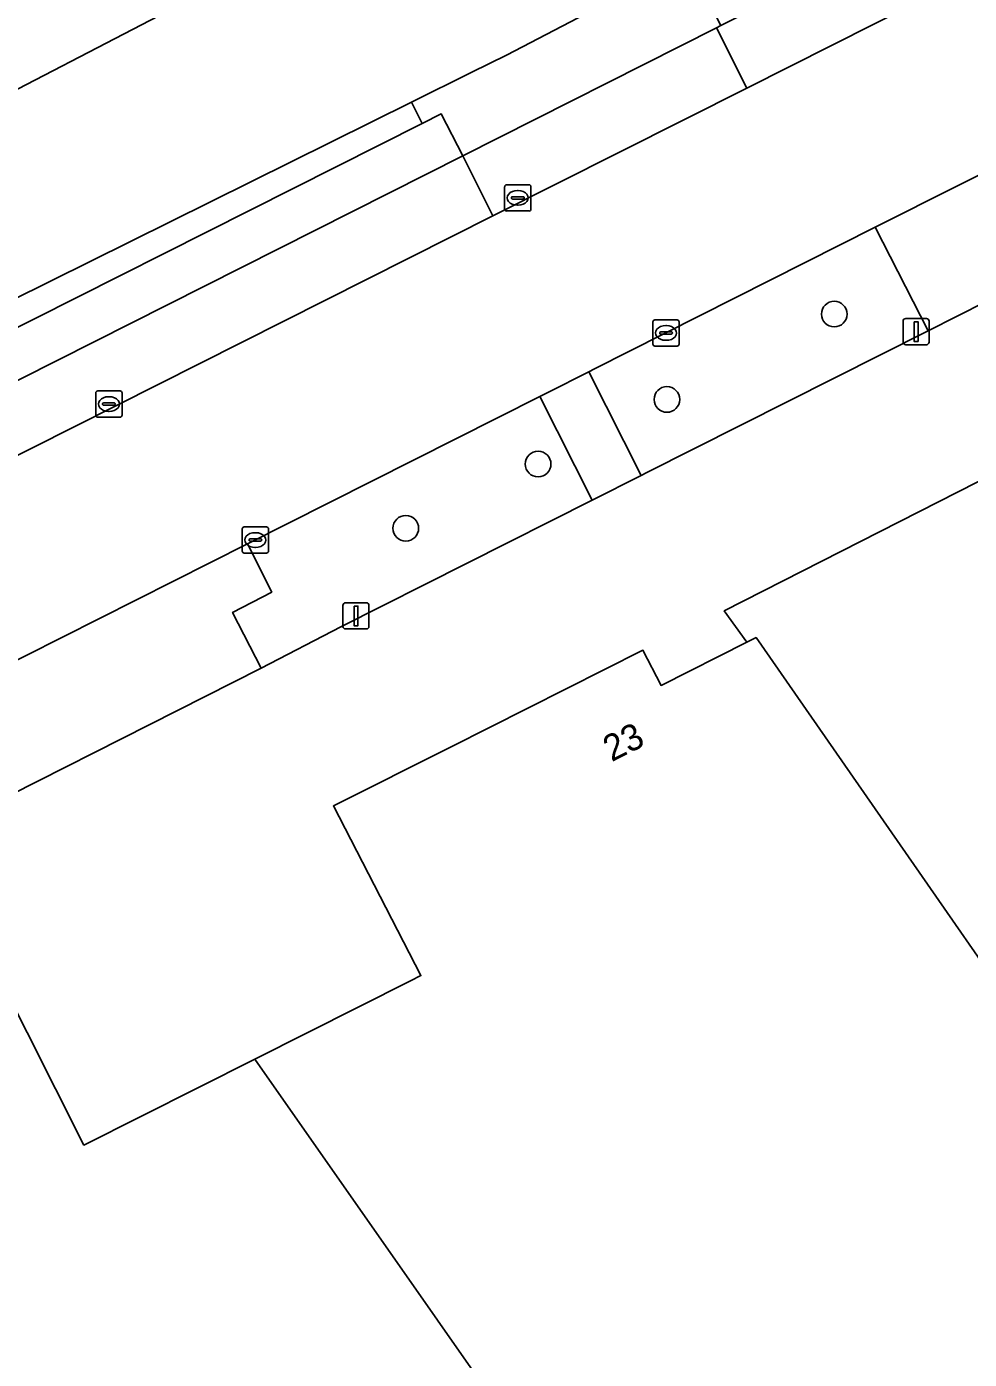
# Model space of a CAD drawing. Extents: x 156702 to 158052, y 387630 to 388992.
# Drawn here: x 157104.6 to 157140.6, y 388253.5 to 388304.3 of the extents above; entities that cross this region are included whole.
import ezdxf

# ---------------------------------------------------------------- set-up
doc = ezdxf.new("R2010")
doc.units = 0
for name, color, linetype in [('IMGEO_Berm_groen', 7, 'Continuous'), ('IMGEO_Boom', 7, 'Continuous'), ('IMGEO_Erf', 7, 'Continuous'), ('IMGEO_Groenvoorziening', 7, 'Continuous'), ('IMGEO_Hek', 7, 'Continuous'), ('IMGEO_Kolk', 7, 'Continuous'), ('IMGEO_Pand', 7, 'Continuous'), ('IMGEO_Pand_nummerreeks', 7, 'Continuous'), ('IMGEO_Parkeervlak_open', 7, 'Continuous'), ('IMGEO_Rijbaan_lokaal_gesloten', 7, 'Continuous'), ('IMGEO_Rijbaan_lokaal_open', 7, 'Continuous'), ('IMGEO_Verkeersbordpaal', 7, 'Continuous'), ('IMGEO_Voetpad_open', 7, 'Continuous')]:
    doc.layers.add(name, color=color, linetype=linetype)

msp = doc.modelspace()

# ---------------------------------------------------------------- linework, layer by layer
at = {"layer": 'IMGEO_Berm_groen'}
for points in [[(157138.985, 388292.726), (157136.976, 388296.673), (157126.271, 388291.273), (157126.055, 388291.164), (157128.049, 388287.211), (157128.27, 388287.322)], [(157126.181, 388286.269), (157124.187, 388290.222), (157114.576, 388285.374), (157113.037, 388284.606), (157113.966, 388282.763), (157112.472, 388281.984), (157113.566, 388279.867), (157116.605, 388281.44)]]:
    msp.add_lwpolyline(points, close=True, dxfattribs=at)
at = {"layer": 'IMGEO_Boom'}
for centre in [(157135.411, 388293.362), (157129.031, 388290.107), (157124.121, 388287.644), (157119.075, 388285.195)]:
    msp.add_circle(centre, 0.489, dxfattribs=at)
at = {"layer": 'IMGEO_Erf'}
for points in [[(157055.318, 388268.856), (157065.932, 388274.591), (157095.174, 388289.455), (157094.853, 388290.096), (157097.304, 388291.355), (157097.614, 388290.696), (157097.881, 388290.831), (157119.289, 388301.443), (157121.594, 388302.586), (157122.912, 388303.239), (157126.545, 388305.126), (157128.281, 388306.017), (157129.856, 388306.814), (157137.907, 388310.886), (157152.903, 388318.564), (157174.095, 388329.453), (157180.461, 388332.701), (157200.119, 388342.587), (157202.298, 388343.699), (157206.748, 388345.97), (157208.141, 388346.681), (157233.238, 388359.337)], [(157122.172, 388339.279), (157131.58, 388321.178), (157130.534, 388320.636), (157127.174, 388318.896), (157111.341, 388310.694), (157112.254, 388308.898), (157113.385, 388306.675), (157098.864, 388299.145), (157097.709, 388298.546), (157097.295, 388299.345), (157088.463, 388294.756), (157088.87, 388293.953), (157087.721, 388293.356), (157073.205, 388285.813), (157071.146, 388289.768), (157053.094, 388280.388)], [(157148.941, 388297.754), (157138.985, 388292.726), (157128.27, 388287.322), (157128.049, 388287.211), (157126.181, 388286.269), (157116.605, 388281.44), (157113.566, 388279.867), (157099.732, 388272.877), (157085.63, 388265.739), (157083.745, 388264.78), (157064.77, 388255.035), (157056.22, 388250.104), (157054.047, 388248.702), (157044.401, 388242.479)], [(157072.863, 388252.591), (157084.801, 388258.647), (157084.478, 388259.333), (157085.367, 388259.787), (157085.926, 388259.25), (157088.898, 388260.696), (157088.742, 388261.5), (157089.628, 388261.947), (157089.986, 388261.264), (157103.546, 388268.114), (157106.805, 388261.679), (157113.32, 388264.949), (157119.249, 388267.935), (157119.653, 388268.139), (157116.316, 388274.608), (157120.809, 388276.868), (157128.117, 388280.546), (157128.809, 388279.204), (157132.082, 388280.851), (157131.214, 388282.046), (157149.786, 388291.491)]]:
    msp.add_lwpolyline(points, dxfattribs=at)
at = {"layer": 'IMGEO_Groenvoorziening'}
msp.add_lwpolyline([(157119.694, 388300.635), (157119.289, 388301.443), (157097.881, 388290.831), (157098.352, 388289.876)], close=True, dxfattribs=at)
at = {"layer": 'IMGEO_Hek'}
msp.add_lwpolyline([(157121.594, 388302.586), (157119.289, 388301.443), (157097.881, 388290.831)], dxfattribs=at)
at = {"layer": 'IMGEO_Kolk'}
for p, q in [((157122.845, 388297.367), (157122.845, 388298.219)), ((157122.92, 388298.293), (157123.772, 388298.293)), ((157123.333, 388298.073), (157123.358, 388298.073)), ((157123.846, 388298.219), (157123.846, 388297.367)), ((157123.104, 388297.787), (157123.104, 388297.799)), ((157123.542, 388297.75), (157123.144, 388297.75)), ((157123.147, 388297.836), (157123.545, 388297.836)), ((157123.356, 388297.513), (157123.331, 388297.513)), ((157123.588, 388297.799), (157123.588, 388297.787)), ((157123.772, 388297.293), (157122.92, 388297.293)), ((157128.496, 388292.216), (157128.496, 388293.068)), ((157128.571, 388293.142), (157129.423, 388293.142)), ((157128.984, 388292.922), (157129.009, 388292.922)), ((157129.497, 388293.068), (157129.497, 388292.216)), ((157128.755, 388292.636), (157128.755, 388292.648)), ((157129.193, 388292.599), (157128.795, 388292.599)), ((157128.798, 388292.685), (157129.196, 388292.685)), ((157129.007, 388292.362), (157128.982, 388292.362)), ((157129.239, 388292.648), (157129.239, 388292.636)), ((157129.423, 388292.142), (157128.571, 388292.142)), ((157107.256, 388289.506), (157107.256, 388290.358)), ((157107.331, 388290.432), (157108.183, 388290.432)), ((157108.257, 388290.358), (157108.257, 388289.506)), ((157107.515, 388289.926), (157107.515, 388289.938)), ((157107.953, 388289.889), (157107.555, 388289.889)), ((157107.558, 388289.975), (157107.956, 388289.975)), ((157107.744, 388290.212), (157107.769, 388290.212)), ((157107.999, 388289.938), (157107.999, 388289.926)), ((157108.183, 388289.432), (157107.331, 388289.432)), ((157107.767, 388289.652), (157107.742, 388289.652)), ((157112.915, 388285.247), (157113.767, 388285.247)), ((157112.84, 388284.321), (157112.84, 388285.173)), ((157113.099, 388284.741), (157113.099, 388284.753)), ((157113.537, 388284.704), (157113.139, 388284.704)), ((157113.142, 388284.79), (157113.54, 388284.79)), ((157113.328, 388285.027), (157113.353, 388285.027)), ((157113.583, 388284.753), (157113.583, 388284.741)), ((157113.841, 388285.173), (157113.841, 388284.321)), ((157113.767, 388284.247), (157112.915, 388284.247)), ((157113.351, 388284.467), (157113.326, 388284.467))]:
    msp.add_line(p, q, dxfattribs=at)
for points in [[(157122.845, 388297.367), (157122.845, 388298.219)], [(157122.92, 388298.293), (157123.772, 388298.293)], [(157123.846, 388298.219), (157123.846, 388297.367)], [(157123.772, 388297.293), (157122.92, 388297.293)], [(157128.496, 388292.216), (157128.496, 388293.068)], [(157128.571, 388293.142), (157129.423, 388293.142)], [(157129.497, 388293.068), (157129.497, 388292.216)], [(157129.423, 388292.142), (157128.571, 388292.142)], [(157107.256, 388289.506), (157107.256, 388290.358)], [(157107.331, 388290.432), (157108.183, 388290.432)], [(157108.257, 388290.358), (157108.257, 388289.506)], [(157108.183, 388289.432), (157107.331, 388289.432)], [(157112.915, 388285.247), (157113.767, 388285.247)], [(157112.84, 388284.321), (157112.84, 388285.173)], [(157113.841, 388285.173), (157113.841, 388284.321)], [(157113.767, 388284.247), (157112.915, 388284.247)]]:
    msp.add_lwpolyline(points, dxfattribs=at)
for centre, radius, start, end in [((157122.922, 388298.217), 0.0765, 91.552, 178.448), ((157122.922, 388298.217), 0.0765, 91.552, 178.448), ((157123.77, 388298.217), 0.0765, 1.552, 88.448), ((157123.77, 388298.217), 0.0765, 1.552, 88.448), ((157123.144, 388297.796), 0.0403, 85.8775, 175.7526), ((157123.141, 388297.786), 0.0366, 178.938, 274.7102), ((157123.545, 388297.793), 0.043, 264.8664, 352.4533), ((157123.549, 388297.798), 0.0386, 1.7309, 96.639), ((157122.922, 388297.369), 0.0765, 181.552, 268.448), ((157122.922, 388297.369), 0.0765, 181.552, 268.448), ((157123.77, 388297.369), 0.0765, 271.552, 358.448), ((157123.77, 388297.369), 0.0765, 271.552, 358.448), ((157128.573, 388293.066), 0.0765, 91.552, 178.448), ((157128.573, 388293.066), 0.0765, 91.552, 178.448), ((157129.421, 388293.066), 0.0765, 1.552, 88.448), ((157129.421, 388293.066), 0.0765, 1.552, 88.448), ((157128.795, 388292.645), 0.0403, 85.8775, 175.7526), ((157128.792, 388292.635), 0.0366, 178.938, 274.7102), ((157129.196, 388292.642), 0.043, 264.8664, 352.4533), ((157129.2, 388292.647), 0.0386, 1.7309, 96.639), ((157128.573, 388292.218), 0.0765, 181.552, 268.448), ((157128.573, 388292.218), 0.0765, 181.552, 268.448), ((157129.421, 388292.218), 0.0765, 271.552, 358.448), ((157129.421, 388292.218), 0.0765, 271.552, 358.448), ((157107.333, 388290.356), 0.0765, 91.552, 178.448), ((157107.333, 388290.356), 0.0765, 91.552, 178.448), ((157108.181, 388290.356), 0.0765, 1.552, 88.448), ((157108.181, 388290.356), 0.0765, 1.552, 88.448), ((157107.555, 388289.935), 0.0403, 85.8775, 175.7526), ((157107.552, 388289.925), 0.0366, 178.938, 274.7102), ((157107.956, 388289.932), 0.043, 264.8664, 352.4533), ((157107.96, 388289.937), 0.0386, 1.7309, 96.639), ((157107.333, 388289.508), 0.0765, 181.552, 268.448), ((157107.333, 388289.508), 0.0765, 181.552, 268.448), ((157108.181, 388289.508), 0.0765, 271.552, 358.448), ((157108.181, 388289.508), 0.0765, 271.552, 358.448), ((157112.917, 388285.171), 0.0765, 91.552, 178.448), ((157112.917, 388285.171), 0.0765, 91.552, 178.448), ((157113.765, 388285.171), 0.0765, 1.552, 88.448), ((157113.765, 388285.171), 0.0765, 1.552, 88.448), ((157113.139, 388284.75), 0.0403, 85.8775, 175.7526), ((157113.136, 388284.74), 0.0366, 178.938, 274.7102), ((157113.54, 388284.747), 0.043, 264.8664, 352.4533), ((157113.544, 388284.752), 0.0386, 1.7309, 96.639), ((157112.917, 388284.323), 0.0765, 181.552, 268.448), ((157112.917, 388284.323), 0.0765, 181.552, 268.448), ((157113.765, 388284.323), 0.0765, 271.552, 358.448), ((157113.765, 388284.323), 0.0765, 271.552, 358.448)]:
    msp.add_arc(centre, radius, start, end, dxfattribs=at)
for centre, major_axis, ratio, start_param, end_param in [((157123.332, 388297.793), (-0.387, 0.002), 0.722429, 4.712389, 7.853982), ((157123.357, 388297.793), (-0.39, 0.002), 0.717154, 1.570796, 4.712389), ((157128.983, 388292.642), (-0.387, 0.002), 0.722429, 4.712389, 7.853982), ((157129.008, 388292.642), (-0.39, 0.002), 0.717154, 1.570796, 4.712389), ((157107.743, 388289.932), (-0.387, 0.002), 0.722429, 4.712389, 7.853982), ((157107.768, 388289.932), (-0.39, 0.002), 0.717154, 1.570796, 4.712389), ((157113.327, 388284.747), (-0.387, 0.002), 0.722429, 4.712389, 7.853982), ((157113.352, 388284.747), (-0.39, 0.002), 0.717154, 1.570796, 4.712389)]:
    msp.add_ellipse(centre, major_axis=major_axis, ratio=ratio, start_param=start_param, end_param=end_param, dxfattribs=at)
at = {"layer": 'IMGEO_Pand'}
msp.add_lwpolyline([(157053.094, 388280.388), (157071.146, 388289.768), (157073.205, 388285.813), (157087.721, 388293.356), (157088.87, 388293.953), (157088.463, 388294.756), (157097.295, 388299.345), (157097.709, 388298.546), (157098.864, 388299.145), (157113.385, 388306.675), (157112.254, 388308.898), (157111.341, 388310.694), (157127.174, 388318.896), (157130.534, 388320.636), (157131.58, 388321.178), (157122.172, 388339.279)], dxfattribs=at)
for points in [[(157150.298, 388290.598), (157150.383, 388290.659), (157149.786, 388291.491), (157131.214, 388282.046), (157132.082, 388280.851), (157132.433, 388281.028), (157148.354, 388258.104), (157151.414, 388253.673), (157168.087, 388265.189)], [(157132.433, 388281.028), (157132.082, 388280.851), (157128.809, 388279.204), (157128.117, 388280.546), (157120.809, 388276.868), (157116.316, 388274.608), (157119.653, 388268.139), (157119.249, 388267.935), (157113.32, 388264.949), (157134.3, 388234.974), (157156.538, 388246.255), (157151.414, 388253.673), (157148.354, 388258.104)], [(157113.32, 388264.949), (157106.805, 388261.679), (157103.546, 388268.114), (157089.986, 388261.264), (157089.628, 388261.947), (157088.742, 388261.5), (157088.898, 388260.696), (157085.926, 388259.25), (157085.367, 388259.787), (157084.478, 388259.333), (157084.801, 388258.647), (157072.863, 388252.591), (157074.168, 388250), (157076.091, 388246.183), (157074.559, 388245.319), (157077.424, 388241.221), (157095.536, 388215.309), (157134.3, 388234.974)]]:
    msp.add_lwpolyline(points, close=True, dxfattribs=at)
at = {"layer": 'IMGEO_Parkeervlak_open'}
msp.add_lwpolyline([(157138.553, 388305.245), (157137.409, 388307.516), (157131.09, 388304.366), (157130.915, 388304.277), (157132.072, 388301.981)], close=True, dxfattribs=at)
msp.add_lwpolyline([(157066.549, 388268.973), (157122.397, 388297.107), (157121.246, 388299.392), (157065.041, 388271.043), (157057.934, 388267.327), (157059.11, 388264.858)], dxfattribs=at)
at = {"layer": 'IMGEO_Rijbaan_lokaal_gesloten'}
for points in [[(157279.127, 388368.703), (157285.498, 388371.81), (157294.645, 388375.709), (157303.766, 388378.867), (157314.242, 388381.65), (157428.83, 388408.527), (157427.649, 388413.564), (157313.182, 388386.746), (157307.564, 388385.322), (157304.11, 388384.347), (157298.594, 388382.628), (157295.094, 388381.431), (157289.829, 388379.374), (157285.802, 388377.632), (157280.387, 388375.114), (157169.957, 388319.498), (157169.378, 388320.773), (157166.981, 388319.566), (157158.272, 388315.179), (157138.553, 388305.245), (157132.072, 388301.981), (157122.397, 388297.107), (157066.549, 388268.973)], [(157064.311, 388259.963), (157069.269, 388262.524), (157081.717, 388268.807), (157083.645, 388269.772), (157096.097, 388276.064), (157113.037, 388284.606), (157114.576, 388285.374), (157124.187, 388290.222), (157124.485, 388290.372), (157126.055, 388291.164), (157126.271, 388291.273), (157136.976, 388296.673), (157146.433, 388301.427), (157146.447, 388301.446), (157171.244, 388314.319), (157180.605, 388319.095), (157279.127, 388368.703)]]:
    msp.add_lwpolyline(points, dxfattribs=at)
at = {"layer": 'IMGEO_Rijbaan_lokaal_open'}
msp.add_lwpolyline([(157096.097, 388276.064), (157096.995, 388274.201), (157098.705, 388275.045), (157099.732, 388272.877), (157113.566, 388279.867), (157112.472, 388281.984), (157113.966, 388282.763), (157113.037, 388284.606)], close=True, dxfattribs=at)
at = {"layer": 'IMGEO_Verkeersbordpaal'}
for p, q in [((157138.035, 388292.293), (157138.035, 388293.093)), ((157138.035, 388293.093), (157138.035, 388292.293)), ((157138.135, 388293.193), (157138.925, 388293.193)), ((157138.925, 388293.193), (157138.135, 388293.193)), ((157139.025, 388293.093), (157139.025, 388292.293)), ((157139.025, 388292.293), (157139.025, 388293.093)), ((157138.925, 388292.193), (157138.135, 388292.193)), ((157138.135, 388292.193), (157138.925, 388292.193)), ((157116.681, 388281.456), (157116.681, 388282.256)), ((157116.681, 388282.256), (157116.681, 388281.456)), ((157116.781, 388282.356), (157117.571, 388282.356)), ((157117.571, 388282.356), (157116.781, 388282.356)), ((157117.671, 388282.256), (157117.671, 388281.456)), ((157117.671, 388281.456), (157117.671, 388282.256)), ((157117.571, 388281.356), (157116.781, 388281.356)), ((157116.781, 388281.356), (157117.571, 388281.356))]:
    msp.add_line(p, q, dxfattribs=at)
for points in [[(157138.455, 388293.068), (157138.605, 388293.068), (157138.605, 388292.318), (157138.455, 388292.318), (157138.455, 388293.068)], [(157117.101, 388282.231), (157117.251, 388282.231), (157117.251, 388281.481), (157117.101, 388281.481), (157117.101, 388282.231)]]:
    msp.add_lwpolyline(points, dxfattribs=at)
for centre, start, end in [((157138.135, 388293.093), 90, 180), ((157138.135, 388293.093), 90, 180), ((157138.925, 388293.093), 0, 90), ((157138.925, 388293.093), 360, 90), ((157138.135, 388292.293), 180, 270), ((157138.135, 388292.293), 180, 270), ((157138.925, 388292.293), 270, 0), ((157138.925, 388292.293), 270, 0), ((157116.781, 388282.256), 90, 180), ((157116.781, 388282.256), 90, 180), ((157117.571, 388282.256), 0, 90), ((157117.571, 388282.256), 360, 90), ((157116.781, 388281.456), 180, 270), ((157116.781, 388281.456), 180, 270), ((157117.571, 388281.456), 270, 0), ((157117.571, 388281.456), 270, 0)]:
    msp.add_arc(centre, 0.1, start, end, dxfattribs=at)
at = {"layer": 'IMGEO_Voetpad_open'}
for points in [[(157130.915, 388304.277), (157131.09, 388304.366), (157130.276, 388305.976), (157129.856, 388306.814), (157128.281, 388306.017), (157126.545, 388305.126), (157122.912, 388303.239), (157121.594, 388302.586), (157119.289, 388301.443), (157119.694, 388300.635), (157120.423, 388301.002), (157121.246, 388299.392)], [(157132.072, 388301.981), (157130.915, 388304.277), (157121.246, 388299.392), (157122.397, 388297.107)], [(157126.055, 388291.164), (157124.485, 388290.372), (157124.187, 388290.222), (157126.181, 388286.269), (157128.049, 388287.211)]]:
    msp.add_lwpolyline(points, close=True, dxfattribs=at)
for points in [[(157121.246, 388299.392), (157120.423, 388301.002), (157119.694, 388300.635), (157098.352, 388289.876), (157097.881, 388290.831), (157097.614, 388290.696), (157095.174, 388289.455), (157095.65, 388288.504), (157064.429, 388272.773)], [(157146.433, 388301.427), (157136.976, 388296.673), (157138.985, 388292.726), (157148.941, 388297.754)], [(157057.048, 388268.872), (157057.934, 388267.327), (157065.041, 388271.043), (157121.246, 388299.392)]]:
    msp.add_lwpolyline(points, dxfattribs=at)

# ---------------------------------------------------------------- texts
at = {"layer": 'IMGEO_Pand_nummerreeks'}
msp.add_text('23', height=1, rotation=26.7113, dxfattribs=at).set_placement((157126.923, 388276.273))

doc.saveas('drawing.dxf')
